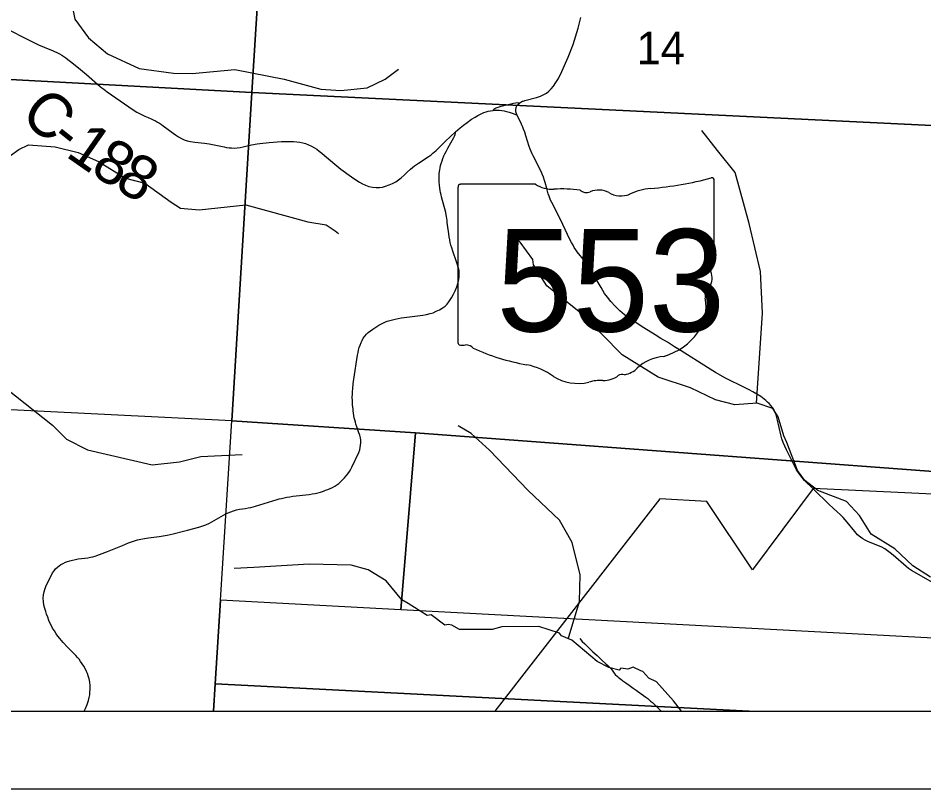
# Model space of a CAD drawing. Extents: x -2.1 to 31.9, y 6.3 to 28.3.
# Drawn here: x 1.952 to 3.117, y 20.344 to 21.336 of the extents above; entities that cross this region are included whole.
import ezdxf

# ---------------------------------------------------------------- set-up
doc = ezdxf.new("R2010")
doc.units = 0
for name, color, linetype in [('Default', 7, 'Continuous'), ('GM_X_City_Street', 7, 'Continuous'), ('GM_X_County_Road', 7, 'Continuous'), ('GM_X_County_Road_Text', 7, 'Continuous'), ('GM_X_Minor_River', 7, 'Continuous'), ('GM_X_Section', 7, 'Continuous'), ('GM_X_Section_Text', 7, 'Continuous'), ('GM_X_State_Location', 7, 'Continuous'), ('GM_X_State_Route', 7, 'Continuous'), ('GM_X_State_Shield', 7, 'Continuous'), ('GM_X_Township_Road', 7, 'Continuous'), ('SH_Cut_Line', 7, 'Continuous'), ('SH_Data', 7, 'Continuous')]:
    doc.layers.add(name, color=color, linetype=linetype)

msp = doc.modelspace()

# ---------------------------------------------------------------- linework, layer by layer
at = {"layer": 'Default'}
for points in [[(0.0344, 26.1105), (0.0344, 20.444), (3.7533, 20.444), (3.8489, 20.5389), (3.9894, 20.6326), (4.16, 20.7203), (4.2895, 20.7662), (4.3023, 20.7658), (4.3091, 20.8714), (4.3751, 21.8979), (4.4168, 22.5238), (4.4383, 22.8067), (4.4651, 23.2405), (4.4901, 23.6442), (4.5473, 24.5954), (4.5667, 24.9084), (4.6032, 25.4816), (4.6286, 25.8765), (3.8625, 25.9158), (3.0763, 25.9555), (2.8034, 25.9683), (2.0757, 26.0047), (0.4641, 26.0883)], [(1.1769, 20.444), (2.2035, 20.444), (2.2056, 20.479), (2.2124, 20.5868), (2.2269, 20.8175), (1.2015, 20.8687)], [(2.565, 20.444), (3.7533, 20.444), (3.8489, 20.5389), (3.8524, 20.5411), (3.8819, 20.56), (3.9131, 20.5819), (3.9243, 20.5893), (3.9388, 20.5991), (3.9535, 20.6088), (3.9664, 20.6173), (3.9829, 20.6284), (3.9898, 20.633), (3.9977, 20.637), (4.0042, 20.6402), (3.7666, 20.6598), (3.2373, 20.718), (2.9743, 20.7306), (2.8967, 20.6256), (2.8379, 20.7139), (2.7774, 20.717)], [(2.8922, 20.444), (3.2442, 20.444), (3.25, 20.5316), (2.4442, 20.5745), (2.2124, 20.5868), (2.2056, 20.479)], [(2.2035, 20.444), (2.8922, 20.444), (2.2056, 20.479)]]:
    msp.add_lwpolyline(points, close=True, dxfattribs=at)
at = {"layer": 'GM_X_City_Street'}
msp.add_lwpolyline([(2.6743, 20.5376), (2.6776, 20.5337), (2.6807, 20.5304), (2.6842, 20.5271), (2.6911, 20.5205), (2.6966, 20.5154), (2.7029, 20.5095), (2.708, 20.505), (2.7104, 20.5029), (2.7121, 20.5011), (2.7133, 20.4998), (2.7146, 20.4985), (2.7167, 20.4954), (2.7185, 20.4929), (2.7201, 20.4911), (2.7229, 20.4886), (2.7247, 20.487), (2.7266, 20.4854), (2.7296, 20.4832), (2.7336, 20.4804), (2.7377, 20.4775), (2.7432, 20.4736), (2.7468, 20.4711), (2.7533, 20.4663), (2.7563, 20.4641), (2.7592, 20.4619), (2.7617, 20.4601), (2.7631, 20.4589), (2.7655, 20.4569), (2.7678, 20.4549), (2.7731, 20.4498), (2.7792, 20.444)], dxfattribs=at)
at = {"layer": 'GM_X_County_Road'}
for points in [[(1.9428, 21.3193), (1.9597, 21.3105), (1.9708, 21.305), (1.9784, 21.3013), (1.993, 21.2953), (1.9965, 21.2939), (1.9991, 21.2928), (2.0019, 21.2914), (2.0052, 21.2897), (2.0084, 21.2879), (2.011, 21.2863), (2.0134, 21.2846), (2.0162, 21.2825), (2.0197, 21.2797), (2.0298, 21.2716), (2.0401, 21.263), (2.0579, 21.2478), (2.06, 21.246), (2.0622, 21.2442), (2.0645, 21.2425), (2.0666, 21.2408), (2.0944, 21.2214), (2.1, 21.2176), (2.105, 21.2145), (2.1091, 21.2123), (2.1152, 21.2094), (2.1193, 21.2077), (2.1231, 21.206), (2.1259, 21.2047), (2.1287, 21.2033), (2.1315, 21.2018), (2.1341, 21.2004), (2.1364, 21.1988), (2.1388, 21.1971), (2.1517, 21.1874), (2.1544, 21.1855), (2.1583, 21.1829), (2.1622, 21.1808), (2.1657, 21.1792), (2.1697, 21.1778), (2.1738, 21.1768), (2.1793, 21.176), (2.1918, 21.1747), (2.1947, 21.1744), (2.198, 21.1738), (2.2022, 21.173), (2.2172, 21.1698), (2.2201, 21.1693), (2.2234, 21.1688), (2.2267, 21.1686), (2.2306, 21.1685), (2.2339, 21.1687), (2.2376, 21.1691), (2.2414, 21.1698), (2.2524, 21.1725), (2.2547, 21.1729), (2.2571, 21.1734), (2.2597, 21.1738), (2.263, 21.1742), (2.2751, 21.1755), (2.2802, 21.176), (2.2854, 21.1764), (2.2909, 21.1767), (2.2958, 21.1768), (2.3015, 21.1768), (2.3061, 21.1767), (2.3104, 21.1763), (2.3143, 21.1759), (2.3181, 21.1752), (2.3219, 21.1741), (2.3257, 21.1726), (2.3293, 21.171), (2.3331, 21.1689), (2.3363, 21.1668), (2.3394, 21.1646), (2.3427, 21.1617), (2.346, 21.1589), (2.3672, 21.1413), (2.3809, 21.1313), (2.3864, 21.1276), (2.3913, 21.1247), (2.3952, 21.1224), (2.399, 21.1206), (2.4033, 21.1191), (2.4079, 21.1181), (2.4125, 21.1177), (2.4169, 21.1177), (2.4207, 21.1183), (2.4248, 21.1195), (2.4293, 21.121), (2.4334, 21.1228), (2.4377, 21.125), (2.4415, 21.1274), (2.4449, 21.1301), (2.4486, 21.1335), (2.4525, 21.1374), (2.4566, 21.1411), (2.4592, 21.1433), (2.462, 21.1454), (2.4643, 21.1471), (2.4672, 21.1489), (2.4808, 21.158), (2.4831, 21.1598), (2.4855, 21.1618), (2.4876, 21.1636), (2.4897, 21.1655), (2.4918, 21.1674), (2.494, 21.1695), (2.5016, 21.1772), (2.5144, 21.1891), (2.5206, 21.1943), (2.5249, 21.1979), (2.5297, 21.2015), (2.5352, 21.2054), (2.5397, 21.2083), (2.5435, 21.2105), (2.546, 21.2117), (2.5485, 21.2129), (2.5512, 21.214), (2.554, 21.215), (2.5567, 21.2159), (2.5597, 21.2165), (2.5629, 21.2169), (2.5652, 21.2171), (2.5678, 21.2172), (2.571, 21.2171), (2.5741, 21.2167), (2.5771, 21.2162), (2.58, 21.2155), (2.5834, 21.2147), (2.5873, 21.2135), (2.5907, 21.212), (2.5937, 21.2107)], [(2.5629, 21.2169), (2.5641, 21.2184), (2.5653, 21.2193), (2.5667, 21.2202), (2.568, 21.2208), (2.5706, 21.2215), (2.5735, 21.2224), (2.5892, 21.2262), (2.5918, 21.2267), (2.5944, 21.227), (2.5975, 21.2268)]]:
    msp.add_lwpolyline(points, dxfattribs=at)
at = {"layer": 'GM_X_Minor_River'}
for points in [[(2.0233, 21.3805), (2.02, 21.3608), (2.025, 21.3342), (2.0428, 21.3103), (2.0672, 21.2895), (2.1078, 21.2706), (2.1518, 21.2646), (2.1761, 21.2643), (2.2307, 21.2697), (2.2944, 21.2569), (2.3415, 21.2441), (2.3673, 21.2426), (2.401, 21.2457), (2.4241, 21.2572), (2.4415, 21.2698)], [(1.7836, 21.1929), (1.7864, 21.1718), (1.8171, 21.1658), (1.8816, 21.1656), (1.9294, 21.155), (1.9423, 21.1589), (1.9533, 21.1665), (1.9654, 21.1726), (1.9999, 21.17), (2.0292, 21.1625), (2.0554, 21.1511), (2.0903, 21.1296), (2.115, 21.1231), (2.1492, 21.0989), (2.1609, 21.0909), (2.1848, 21.0891), (2.2451, 21.0953), (2.3248, 21.0734), (2.3483, 21.0697), (2.3597, 21.0621), (2.3643, 21.0587)], [(2.9017, 20.8402), (2.9095, 20.9558), (2.9066, 21.0095), (2.8922, 21.0714), (2.8742, 21.1369), (2.8516, 21.1654), (2.8312, 21.1911)], [(3.1252, 20.6163), (3.1026, 20.6311), (3.0795, 20.6527), (3.049, 20.6716), (3.0339, 20.6956), (3.0174, 20.7136), (2.9804, 20.7277), (2.9638, 20.7407), (2.9544, 20.7535), (2.9407, 20.7897), (2.9368, 20.7981), (2.9296, 20.8227), (2.9228, 20.8335), (2.9026, 20.8402), (2.8738, 20.8381), (2.849, 20.8446), (2.8166, 20.8601), (2.7751, 20.8735), (2.7287, 20.9024), (2.6777, 20.9541), (2.632, 20.9912), (2.6147, 21.0184), (2.6141, 21.0249), (2.5978, 21.0474), (2.5919, 21.0529), (2.5888, 21.0546)], [(1.816, 20.9458), (1.8539, 20.9214), (1.8966, 20.8965), (1.9193, 20.8726), (1.9363, 20.8595), (1.9965, 20.8117), (2.0144, 20.794), (2.0412, 20.7803), (2.1246, 20.7609), (2.1595, 20.7647), (2.1873, 20.7718), (2.2402, 20.774)], [(2.6601, 20.5383), (2.6602, 20.5396), (2.6741, 20.5851), (2.6748, 20.6193), (2.6647, 20.661), (2.6485, 20.6896), (2.6081, 20.7277), (2.5583, 20.7798), (2.5348, 20.8011), (2.518, 20.8111)], [(2.8052, 20.444), (2.7951, 20.4574), (2.7731, 20.4817), (2.7633, 20.4866), (2.7553, 20.495), (2.7531, 20.4957), (2.7432, 20.5006), (2.7361, 20.4979), (2.7274, 20.4994), (2.7251, 20.4968), (2.7119, 20.5002), (2.6967, 20.5077), (2.6642, 20.5354), (2.651, 20.5407), (2.6483, 20.5445), (2.6219, 20.5528), (2.5742, 20.5523), (2.5617, 20.5492), (2.5198, 20.5491), (2.51, 20.5548), (2.505, 20.5555), (2.5009, 20.5548), (2.4831, 20.568), (2.4782, 20.5672), (2.4536, 20.5824), (2.4457, 20.5873), (2.4256, 20.6116), (2.4025, 20.6256), (2.3806, 20.6316), (2.3266, 20.633), (2.2551, 20.6286), (2.2302, 20.6274)]]:
    msp.add_lwpolyline(points, dxfattribs=at)
at = {"layer": 'GM_X_Section'}
for points in [[(1.2501, 21.725), (2.2801, 21.6751), (2.2526, 21.24), (1.2244, 21.2953)], [(2.2801, 21.6751), (3.3214, 21.6276), (3.295, 21.1893), (2.2526, 21.24)], [(2.2526, 21.24), (2.2269, 20.8175), (1.2015, 20.8687), (1.2244, 21.2953)], [(3.295, 21.1893), (3.2668, 20.742), (2.4633, 20.8019), (2.2269, 20.8175), (2.2526, 21.24)], [(2.4633, 20.8019), (2.4442, 20.5745), (2.2124, 20.5868), (2.2269, 20.8175)], [(3.2668, 20.742), (3.25, 20.5316), (2.4442, 20.5745), (2.4633, 20.8019)]]:
    msp.add_lwpolyline(points, close=True, dxfattribs=at)
at = {"layer": 'GM_X_State_Route'}
for points in [[(2.9753, 20.7293), (2.9745, 20.7301), (2.9635, 20.7408), (2.9602, 20.7446), (2.9573, 20.7483), (2.9547, 20.752), (2.9527, 20.7554), (2.9463, 20.7681), (2.94, 20.7803), (2.9379, 20.7847), (2.936, 20.7894), (2.9344, 20.7942), (2.9329, 20.7995), (2.9287, 20.8182), (2.9278, 20.8218), (2.9269, 20.8253), (2.9258, 20.8284), (2.9249, 20.8305), (2.9236, 20.8328), (2.9219, 20.8351), (2.9202, 20.8373), (2.918, 20.8396), (2.9159, 20.8417), (2.9136, 20.8437), (2.9114, 20.8455), (2.907, 20.8487), (2.9021, 20.8516), (2.8969, 20.8546), (2.892, 20.8572), (2.8861, 20.8602), (2.8618, 20.8725), (2.8488, 20.8798), (2.8386, 20.886), (2.8046, 20.9075), (2.796, 20.9129), (2.787, 20.9185), (2.7786, 20.9236), (2.7714, 20.9281), (2.7567, 20.9372), (2.7457, 20.9444), (2.7383, 20.9493), (2.732, 20.9539), (2.726, 20.959), (2.7198, 20.9649), (2.7144, 20.9709), (2.7099, 20.9764), (2.7063, 20.9815), (2.7017, 20.9889), (2.6921, 21.0053), (2.6898, 21.0093), (2.6879, 21.0125), (2.6858, 21.0156), (2.6836, 21.0189), (2.6807, 21.0228), (2.6712, 21.0351), (2.6693, 21.0377), (2.6673, 21.0406), (2.6657, 21.0434), (2.6637, 21.047), (2.6618, 21.0508), (2.6496, 21.0764), (2.6383, 21.0984), (2.6369, 21.1014), (2.6359, 21.1038), (2.6349, 21.1065), (2.6338, 21.1094), (2.6328, 21.1129), (2.6319, 21.1163), (2.6298, 21.1242), (2.6291, 21.1268), (2.6279, 21.131), (2.6266, 21.1339), (2.6246, 21.1384), (2.6146, 21.1584), (2.6133, 21.1611), (2.612, 21.1642), (2.6108, 21.1671), (2.6095, 21.1705), (2.6052, 21.184), (2.6036, 21.1889), (2.6022, 21.1928), (2.6013, 21.1952), (2.6004, 21.1972), (2.5995, 21.1991), (2.5937, 21.2107), (2.5933, 21.2116), (2.5929, 21.2127), (2.5925, 21.2139), (2.5922, 21.2149), (2.5921, 21.2159), (2.592, 21.2169), (2.5921, 21.2179), (2.5922, 21.2189), (2.5924, 21.2198), (2.5927, 21.2207), (2.5931, 21.2217), (2.5936, 21.2226), (2.5942, 21.2235), (2.5949, 21.2245), (2.5958, 21.2254), (2.5967, 21.2262), (2.5975, 21.2268), (2.5987, 21.2276), (2.5999, 21.2282), (2.6009, 21.2286), (2.6017, 21.2289), (2.6028, 21.2292), (2.6039, 21.2296), (2.6187, 21.2335), (2.6241, 21.2353), (2.6281, 21.2372), (2.6314, 21.2392), (2.6344, 21.2416), (2.6376, 21.2447), (2.6404, 21.2481), (2.6437, 21.2527), (2.6469, 21.2581), (2.6514, 21.267), (2.6594, 21.2853), (2.6657, 21.3015), (2.6724, 21.3228), (2.6758, 21.3362)], [(3.1529, 20.5955), (3.1009, 20.6249), (3.0972, 20.6274), (3.0941, 20.6299), (3.0772, 20.6447), (3.0737, 20.6477), (3.0702, 20.6504), (3.0665, 20.6527), (3.0628, 20.6549), (3.0577, 20.6573), (3.0458, 20.6619), (3.0414, 20.6639), (3.0383, 20.6658), (3.0354, 20.6678), (3.0317, 20.671), (3.028, 20.6749), (3.0183, 20.687), (3.0158, 20.6901), (3.0129, 20.6932), (3.0092, 20.6969), (3.0054, 20.7004), (3.0001, 20.7051), (2.9946, 20.7102), (2.9753, 20.7293)]]:
    msp.add_lwpolyline(points, dxfattribs=at)
at = {"layer": 'GM_X_State_Shield'}
for p, q in [((2.5178, 21.1183), (2.5178, 20.9182)), ((2.6175, 21.1218), (2.521, 21.1218)), ((2.8474, 21.022), (2.8474, 21.1267)), ((2.8473, 21.0221), (2.8474, 21.022))]:
    msp.add_line(p, q, dxfattribs=at)
for centre, major_axis, start_param, end_param in [((2.73, 21.3946), (0.3495, 0), 4.814394, 5.042369), ((2.8437, 21.1272), (0.00367, 0), 6.141152, 7.989035), ((2.5216, 21.1187), (0.00382, 0), 1.712693, 3.28349), ((2.6405, 21.145), (0.037, 0), 4.042523, 4.731795), ((2.6528, 21.0094), (0.133, 0), 1.404758, 1.657858), ((2.7745, 21.0606), (0.0703, 0), 1.699011, 2.107814), ((2.683, 21.1198), (0.0107, 0), 3.836095, 5.185415), ((2.6987, 21.0967), (0.0222, 0), 0.950623, 2.079405), ((2.7274, 21.1284), (0.0267, 0), 4.081561, 5.145723), ((2.8465, 21.0144), (0.00568, 0), 1.883978, 3.671073), ((2.8104, 21.0011), (0.0341, 0), 5.934695, 6.695948), ((2.8435, 21.0216), (0.00393, 0), 5.05454, 6.418171), ((2.8605, 20.9782), (0.0248, 0), 2.387724, 3.262537), ((2.7495, 20.9649), (0.0874, 0), 5.101752, 6.440018), ((2.5216, 20.9178), (0.00385, 0), 3.00124, 4.508301), ((2.5222, 20.9382), (0.0294, 0), 4.665946, 4.897461), ((2.5282, 20.9067), (0.0106, 0), 0.519207, 1.627899), ((2.662, 21.0865), (0.2524, 0), 4.195997, 4.488961), ((2.7864, 20.862), (0.0479, 0), 1.647645, 2.488434), ((2.5868, 20.8283), (0.079, 0), 0.823519, 1.323587), ((2.7257, 20.8988), (0.0282, 0), 4.937069, 5.64225), ((2.6722, 20.9057), (0.0501, 0), 4.026481, 4.996735), ((2.7048, 20.8907), (0.0267, 0), 4.691044, 5.507374), ((2.7289, 20.8713), (0.00752, 0), 1.147584, 2.315152), ((2.7011, 20.8365), (0.0412, 0), 1.495662, 1.94098)]:
    msp.add_ellipse(centre, major_axis=major_axis, ratio=0.8, start_param=start_param, end_param=end_param, dxfattribs=at)
at = {"layer": 'GM_X_Township_Road'}
msp.add_lwpolyline([(2.0371, 20.444), (2.0389, 20.4474), (2.041, 20.4525), (2.042, 20.4553), (2.0428, 20.4578), (2.0436, 20.4614), (2.0442, 20.4648), (2.0446, 20.4682), (2.0448, 20.4721), (2.0447, 20.4768), (2.0443, 20.4814), (2.0435, 20.4855), (2.0423, 20.4894), (2.0412, 20.4924), (2.04, 20.4952), (2.0382, 20.4989), (2.0366, 20.5019), (2.0347, 20.505), (2.0326, 20.508), (2.0307, 20.5107), (2.0285, 20.5132), (2.0263, 20.5156), (2.0157, 20.5263), (2.0102, 20.5325), (2.0059, 20.5374), (2.0034, 20.5405), (2.0013, 20.5433), (1.9988, 20.5471), (1.9966, 20.5509), (1.9946, 20.5546), (1.9931, 20.5577), (1.9918, 20.5608), (1.9902, 20.565), (1.9889, 20.5686), (1.9877, 20.5723), (1.9865, 20.5761), (1.9854, 20.5804), (1.9847, 20.5849), (1.9845, 20.5895), (1.9848, 20.5936), (1.9855, 20.5973), (1.9866, 20.6007), (1.9879, 20.6042), (1.9897, 20.6081), (1.9952, 20.6191), (1.9966, 20.6218), (1.9985, 20.6246), (2.0004, 20.6269), (2.0027, 20.6292), (2.0049, 20.6309), (2.0073, 20.6325), (2.01, 20.634), (2.013, 20.6355), (2.0159, 20.6365), (2.0187, 20.6374), (2.0221, 20.6384), (2.0259, 20.6392), (2.0296, 20.6399), (2.0338, 20.6404), (2.0381, 20.6409), (2.0418, 20.6414), (2.0451, 20.642), (2.0484, 20.6426), (2.0511, 20.6434), (2.0535, 20.6442), (2.067, 20.6493), (2.0863, 20.6573), (2.0902, 20.659), (2.0941, 20.6605), (2.0979, 20.6619), (2.1019, 20.6631), (2.1058, 20.6642), (2.1099, 20.6651), (2.1148, 20.666), (2.12, 20.6668), (2.1335, 20.6688), (2.1387, 20.6696), (2.1439, 20.6704), (2.1478, 20.6712), (2.1514, 20.672), (2.165, 20.6756), (2.1698, 20.677), (2.1846, 20.6808), (2.1895, 20.6824), (2.1935, 20.6839), (2.1982, 20.686), (2.2103, 20.6927), (2.2134, 20.6946), (2.2161, 20.6961), (2.2192, 20.6978), (2.2223, 20.6992), (2.2258, 20.7006), (2.2293, 20.7018), (2.2329, 20.7028), (2.2368, 20.7037), (2.2405, 20.7044), (2.2442, 20.7049), (2.2481, 20.7055), (2.2514, 20.7061), (2.2545, 20.7069), (2.2575, 20.7078), (2.2851, 20.7162), (2.288, 20.717), (2.2909, 20.7177), (2.2942, 20.7185), (2.2979, 20.7192), (2.3016, 20.7198), (2.3056, 20.7204), (2.3099, 20.7209), (2.3223, 20.7223), (2.3263, 20.7228), (2.3303, 20.7234), (2.334, 20.7242), (2.3375, 20.725), (2.3408, 20.7259), (2.3447, 20.7272), (2.3476, 20.7281), (2.3505, 20.7292), (2.3535, 20.7305), (2.3566, 20.7319), (2.3594, 20.7335), (2.3621, 20.7353), (2.3644, 20.737), (2.3669, 20.7391), (2.3693, 20.7414), (2.3718, 20.7441), (2.3741, 20.7467), (2.3761, 20.7492), (2.3782, 20.7523), (2.38, 20.7553), (2.3813, 20.7578), (2.3902, 20.7769), (2.3914, 20.78), (2.3922, 20.7832), (2.3926, 20.7863), (2.3928, 20.7893), (2.3927, 20.7926), (2.3923, 20.7955), (2.3915, 20.7989), (2.3905, 20.8022), (2.3877, 20.8099), (2.3866, 20.8131), (2.3858, 20.8157), (2.385, 20.8186), (2.3844, 20.8214), (2.3838, 20.8244), (2.3834, 20.8274), (2.383, 20.8302), (2.3828, 20.8329), (2.3823, 20.8376), (2.382, 20.8432), (2.3819, 20.8481), (2.382, 20.8516), (2.3822, 20.8554), (2.3825, 20.8586), (2.3832, 20.8653), (2.3839, 20.871), (2.3887, 20.9021), (2.3893, 20.9053), (2.39, 20.9086), (2.3909, 20.9118), (2.392, 20.915), (2.3931, 20.9181), (2.3944, 20.9208), (2.396, 20.9237), (2.398, 20.9265), (2.4002, 20.9292), (2.4025, 20.9312), (2.4052, 20.9334), (2.4081, 20.9354), (2.416, 20.9404), (2.4185, 20.942), (2.4211, 20.9433), (2.4239, 20.9445), (2.4268, 20.9457), (2.43, 20.9467), (2.4334, 20.9475), (2.437, 20.9483), (2.441, 20.9491), (2.4448, 20.9498), (2.4487, 20.9504), (2.4724, 20.9535), (2.4774, 20.9543), (2.4819, 20.9554), (2.4859, 20.9566), (2.4899, 20.9584), (2.494, 20.9604), (2.4974, 20.9625), (2.5012, 20.9651), (2.5039, 20.9678), (2.507, 20.9717), (2.5095, 20.9757), (2.5121, 20.9805), (2.514, 20.9848), (2.5161, 20.99), (2.5179, 20.9953), (2.5189, 20.9994), (2.5194, 21.0028), (2.5195, 21.0058), (2.5194, 21.0081), (2.5192, 21.0106), (2.5187, 21.0128), (2.5181, 21.0152), (2.5172, 21.0184), (2.516, 21.0221), (2.5112, 21.0359), (2.5098, 21.0402), (2.5087, 21.0436), (2.5079, 21.0468), (2.5072, 21.0503), (2.5065, 21.0541), (2.5059, 21.0581), (2.5043, 21.0697), (2.504, 21.0725), (2.5037, 21.0752), (2.5033, 21.0777), (2.503, 21.0802), (2.5026, 21.0826), (2.502, 21.0855), (2.4967, 21.1057), (2.4961, 21.1084), (2.4954, 21.1111), (2.4949, 21.1138), (2.4944, 21.1167), (2.494, 21.1206), (2.4936, 21.1249), (2.4935, 21.1298), (2.4935, 21.1326), (2.4937, 21.1354), (2.494, 21.1381), (2.4943, 21.1404), (2.4948, 21.1431), (2.4954, 21.1459), (2.4962, 21.1487), (2.4973, 21.1519), (2.4983, 21.155), (2.4997, 21.1583), (2.5009, 21.1611), (2.5024, 21.1642), (2.5046, 21.1683), (2.5124, 21.1818), (2.5134, 21.1838), (2.5141, 21.1857), (2.5145, 21.1875), (2.5144, 21.1891)], dxfattribs=at)
at = {"layer": 'SH_Cut_Line'}
msp.add_lwpolyline([(0.0344, 27.244), (0.0344, 20.444), (3.7533, 20.444)], dxfattribs=at)
at = {"layer": 'SH_Data'}
for p, q in [((0.0344, 20.444), (6.8344, 20.444)), ((-0.0656, 20.344), (6.9344, 20.344))]:
    msp.add_line(p, q, dxfattribs=at)

# ---------------------------------------------------------------- texts
at = {"layer": 'GM_X_County_Road_Text'}
for s, rotation, p in [('C', 318.857, (1.953, 21.2081)), ('-', 321.3811, (1.9902, 21.1757)), ('1', 325.1055, (2.0117, 21.1587)), ('8', 328.1275, (2.0431, 21.1369)), ('8', 329.4883, (2.0741, 21.1176))]:
    msp.add_text(s, height=0.0568, rotation=rotation, dxfattribs=at).set_placement(p)
at = {"layer": 'GM_X_Section_Text'}
msp.add_text('14', height=0.04186, rotation=0, dxfattribs=at).set_placement((2.7474, 21.2763))
at = {"layer": 'GM_X_State_Location'}
for s in ['s', 'r']:
    msp.add_text(s, height=0.000189, dxfattribs=at).set_placement((2.6789, 21.005))
msp.add_text('553', height=0.000189, rotation=0, dxfattribs=at).set_placement((2.612, 20.9912))
at = {"layer": 'GM_X_State_Shield'}
msp.add_text('553', height=0.13184, dxfattribs=at).set_placement((2.5672, 20.9323))

doc.saveas('drawing.dxf')
